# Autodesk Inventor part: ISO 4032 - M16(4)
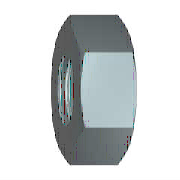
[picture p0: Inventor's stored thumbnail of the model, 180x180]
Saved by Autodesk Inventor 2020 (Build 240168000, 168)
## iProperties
IsCustomPart: 0
Created: 2019-01
Part Number: ISO 4032 - M16(4)
Material: Nerezová ocel 440C
Description: Šestihranné matice, styl 1 – výrobní řada A a B
Document SubType Name: Modeling
Standard: ISO 4032
Designer: doma
Standard Revision: Fourth edition 2012-12-15
Standards Organization: ISO
Language: cs-CZ
Size Designation: M16
Categories: <MemberInstance><Categories><Category DisplayName="Spojovací materiál" InternalName="e4da775c-781d-43d5-af7c-5136215cf5a6" Mnemonic="FSTN"><Category DisplayName
Density: 7.75 g/cm^3
Appearance: Pololeštěná
Mass: 39.003 g
Surface Area: 24.3027 cm^2
Volume: 5.03265 cm^3
Author: doma
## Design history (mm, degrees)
sketch "Náčrt1"
  geometry: L1 (-13.856, 0)-(-6.928, 12); L2 (-6.928, 12)-(6.928, 12); L3 (6.928, 12)-(13.856, 0); L4 (13.856, 0)-(6.928, -12); L5 (6.928, -12)-(-6.928, -12); L6 (-6.928, -12)-(-13.856, 0); 2 further points
  constraints: 12 end point, 1 coincident, 1 horizontal, 11 other
  dimensions: "d0" = 27.71281 distance of L3.end L1.start (= 1.1547 x SW)
extrude "Těleso" new body sketch "Náčrt1" distance "d1" = 14.8 (= KOH); taper "d2" = 0 deg
sketch "Náčrt2"
  geometry: L1 (0, 6.928)-(0, 13.856) reference; L2 (0, 13.856)-(14.8, 13.856) reference; L3 (14.8, 6.928)-(14.8, 13.856) reference; L4 (-2.96, 0)-(17.76, 0) reference; L5 (1.505, 13.856)-(0, 11.25); L6 (13.295, 13.856)-(14.8, 11.25)
  constraints: 4 end point, 4 point on line
  dimensions: "d3" = 30 deg angle of L1 L5 (= ANG1); "d4" = 30 deg angle of L3 L6 (= ANG2); "d5" = 22.5 diameter of L5.end L4 (= SW0); "d6" = 22.5 diameter of L6.end L4 (= SW01)
revolve "Zkosení1" sketch "Náčrt2" stored, may be unused: angle "d7" = 90 deg
sketch "Náčrt3"
  geometry: 4 further points
  constraints: 1 coincident, 1 other
hole "Závit" sketch "Náčrt3" at (0, 0) diameter "d25" = 13.835; stored, may be unused: countersink angle "d29" = 82 deg, drill point angle "d31" = 118 deg; dims "d26" = 6, "d27" = 4, "d28" = 2, "d30" = 8
workaxis "Work Axis1"
workplane "Work Plane1"
body "Solid1"
chamfer "Zkosení2" distance "d8" = 1.08253 (= -0.5 x GD1 + 0.5 x NND); stored, may be unused: angle "d9" = 30 deg, second distance "d40" = 1.08253 (= -0.5 x GD1 + 0.5 x NND)
chamfer "Zkosení3" distance "d10" = 1.08253 (= -0.5 x GD1 + 0.5 x NND); stored, may be unused: angle "d11" = 30 deg, second distance "d41" = 1.08253 (= -0.5 x GD1 + 0.5 x NND)
other parameters: "ANG1" = 30 deg [user parameter; used in 1 equation term], "ANG2" = 30 deg [user parameter; used in 1 equation term], "NND" = 16 [user parameter; used in 4 equation terms], "KOH" = 14.8 [user parameter; used in 1 equation term], "SW" = 24 [user parameter; used in 2 equation terms], "SW0" = 22.5 [user parameter; used in 2 equation terms], "SW01" = 22.5 (= SW0) [user parameter; used in 1 equation term], "GD1" = 13.83494 (computed from THREADDIA, PTC, TOA) [user parameter; used in 4 equation terms], "d13" = 0, "d14" = 0, "d39" = 0, "d42" = 0, "GUL" = 1.08253 (= 0.541266 x PTC) [user parameter], "TPU" = 5 (computed from PTC) [user parameter], "THREADDIA" = 16 [user parameter; used in 1 equation term], "TOA" = 30 deg [user parameter; used in 1 equation term], "PTC" = 2 [user parameter; used in 4 equation terms], "E0" = 27.72 (= 1.155 x SW) [user parameter], "GAL" = 1.08253 (= 0.541266 x PTC) [user parameter]
